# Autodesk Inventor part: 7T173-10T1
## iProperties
Created: 2008-09
Part Number: 7T173-10T1
Document SubType Name: Modeling
Designer: Darius
Author: Darius
Translation Standard: STEP AP203
File Name: 7T173-10T.STEP
Preprocessor: SolidWorks 2003240
Postprocessor: Build: 272, Release: 10 SP3a - Date: Thu 12/15/2005
Sent Units: MILLIMETERS
Uncertainty: 1e-05
